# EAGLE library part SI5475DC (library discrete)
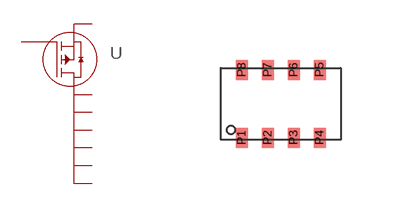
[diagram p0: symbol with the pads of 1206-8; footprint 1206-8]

Designator prefix U

## SI5475DC  [1206-8]
P1  D  pas
P2  D  pas
P3  D  pas
P4  G  pas
P5  S  pas
P6  D  pas
P7  D  pas
P8  D  pas

## Footprint 1206-8 (pad centres in mm)
smd 0.3 x 0.5: P1 -0.975,-0.85; P2 -0.325,-0.85; P3 0.325,-0.85; P4 0.975,-0.85; P5 0.975,0.85; P6 0.325,0.85; P7 -0.325,0.85; P8 -0.975,0.85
